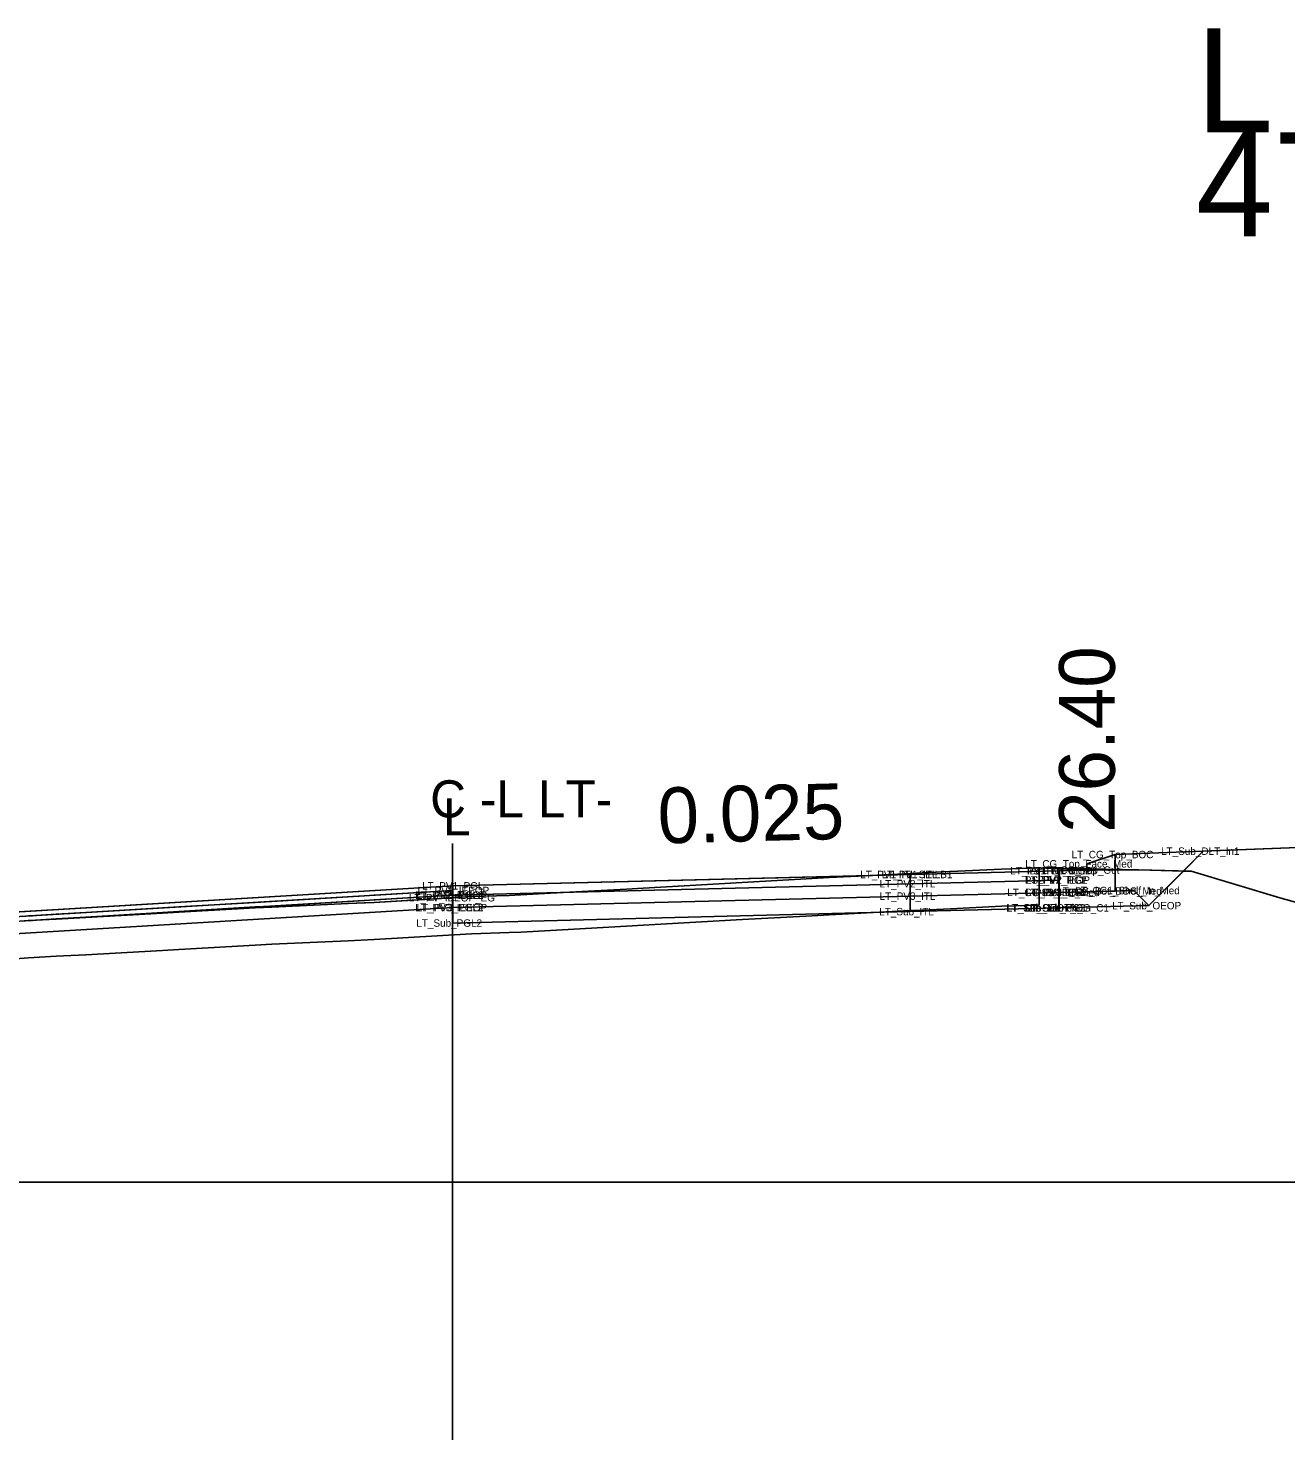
# Model space of a CAD drawing. Extents: x 2177029 to 2201446, y 59897 to 78390.
# Drawn here: x 2200201.31 to 2200235.15, y 68400.38 to 68438.35 of the extents above; entities that cross this region are included whole.
import ezdxf

# ---------------------------------------------------------------- set-up
doc = ezdxf.new("R2010")
doc.units = 0
for name, color, linetype in [('Exist CMT Pavement', 7, 'Continuous'), ('Exist Cross Section Cell', 7, 'Continuous'), ('Exist PHM Roadway Shape', 7, 'Continuous'), ('Exist XS Ground Line', 7, 'Continuous'), ('Old_Level_11', 7, 'Continuous'), ('Prop CMT Conc Surface', 7, 'Continuous'), ('Prop CMT Concrete Structures', 7, 'Continuous'), ('Prop CMT Guardrail Graphics', 7, 'Continuous'), ('Prop CMT Pvmt Course 1', 7, 'Continuous'), ('Prop CMT Pvmt Course 1 CG', 7, 'Continuous'), ('Prop CMT Pvmt Course 2', 7, 'Continuous'), ('Prop CMT Pvmt Course 2 CG', 7, 'Continuous'), ('Prop CMT Pvmt Course 3', 7, 'Continuous'), ('Prop CMT Pvmt Course 4', 7, 'Continuous'), ('Prop CMT Pvmt Surface', 7, 'Continuous'), ('Prop CMT Pvmt Wedge Surface 1', 7, 'Continuous'), ('Prop CMT Slope Grass', 7, 'Continuous'), ('Prop CMT Subgrade Earthwork', 7, 'Continuous'), ('Prop CMT Top Wall Envelope', 7, 'Continuous'), ('Prop Hatching', 7, 'Continuous'), ('Prop Horizontal Alignment', 7, 'Continuous'), ('Prop Retaining Wall', 7, 'Continuous'), ('Prop Terminator CELL', 7, 'Continuous'), ('Prop XS Side Slope Text', 7, 'Continuous'), ('Scratch_Level_0', 7, 'Continuous'), ('Scratch_Level_9', 7, 'Continuous')]:
    doc.layers.add(name, color=color, linetype=linetype)

msp = doc.modelspace()

# ---------------------------------------------------------------- linework, layer by layer
at = {"layer": 'Exist CMT Pavement'}
msp.add_line((2200212.731, 68400.378), (2200212.731, 68416.424), dxfattribs=at)
at = {"layer": 'Exist Cross Section Cell'}
msp.add_line((2200042.732, 68407.31), (2200242.732, 68407.31), dxfattribs=at)
at = {"layer": 'Exist XS Ground Line'}
msp.add_lwpolyline([(2200200.854, 68414.311), (2200201.316, 68414.346), (2200202.064, 68414.385), (2200202.862, 68414.428), (2200204.922, 68414.544), (2200205.363, 68414.569), (2200207.419, 68414.685), (2200207.863, 68414.709), (2200209.917, 68414.802), (2200210.615, 68414.837), (2200213.237, 68414.991), (2200214.251, 68415.022), (2200214.563, 68415.039), (2200215.363, 68415.082), (2200217.409, 68415.195), (2200217.863, 68415.219), (2200219.907, 68415.339), (2200220.363, 68415.365), (2200222.404, 68415.478), (2200222.863, 68415.502), (2200224.902, 68415.607), (2200225.363, 68415.63), (2200226.132, 68415.666), (2200227.498, 68415.73), (2200228.519, 68415.762), (2200231.202, 68415.714), (2200232.605, 68415.672), (2200234.99, 68414.959), (2200242.732, 68412.814)], dxfattribs=at)
at = {"layer": 'Prop CMT Conc Surface'}
for points in [[(2200212.732, 68415.155), (2200186.438, 68413.577)], [(2200212.732, 68415.28), (2200212.732, 68415.03), (2200212.732, 68415.03), (2200212.732, 68415.155)]]:
    msp.add_lwpolyline(points, dxfattribs=at)
at = {"layer": 'Prop CMT Concrete Structures'}
for p, q in [((2200212.732, 68415.28), (2200225.043, 68415.587)), ((2200225.043, 68415.587), (2200225.042, 68415.587)), ((2200229.042, 68415.687), (2200229.05, 68415.688)), ((2200229.05, 68415.688), (2200229.052, 68415.688)), ((2200212.732, 68415.28), (2200176.732, 68413.12))]:
    msp.add_line(p, q, dxfattribs=at)
at = {"layer": 'Prop CMT Guardrail Graphics'}
for points in [[(2200212.732, 68415.28), (2200212.732, 68414.696)], [(2200212.732, 68414.696), (2200176.732, 68412.536)]]:
    msp.add_lwpolyline(points, dxfattribs=at)
at = {"layer": 'Prop CMT Pvmt Course 1'}
for points in [[(2200212.732, 68414.961), (2200210.615, 68414.837), (2200210.363, 68414.822), (2200209.917, 68414.802), (2200207.863, 68414.709), (2200207.419, 68414.685), (2200205.363, 68414.569), (2200204.922, 68414.544), (2200202.862, 68414.428), (2200202.064, 68414.385), (2200201.505, 68414.356), (2200201.424, 68414.351), (2200201.359, 68414.348)], [(2200201.424, 68414.352), (2200201.505, 68414.357), (2200202.064, 68414.39), (2200202.862, 68414.438), (2200204.922, 68414.562), (2200205.363, 68414.588), (2200207.419, 68414.712), (2200207.863, 68414.738), (2200209.917, 68414.861), (2200210.363, 68414.888), (2200210.615, 68414.903), (2200212.732, 68415.03)], [(2200212.732, 68415.03), (2200212.732, 68414.961)], [(2200201.359, 68414.348), (2200201.424, 68414.352)]]:
    msp.add_lwpolyline(points, dxfattribs=at)
at = {"layer": 'Prop CMT Pvmt Course 1 CG'}
for points in [[(2200229.042, 68415.104), (2200225.042, 68415.004)], [(2200225.042, 68415.004), (2200225.042, 68414.587)], [(2200229.042, 68414.687), (2200229.042, 68415.104)], [(2200225.042, 68414.587), (2200229.042, 68414.687)]]:
    msp.add_lwpolyline(points, dxfattribs=at)
at = {"layer": 'Prop CMT Pvmt Course 2'}
for points in [[(2200212.732, 68414.696), (2200225.042, 68415.004)], [(2200225.042, 68415.004), (2200225.042, 68414.587)], [(2200229.042, 68415.104), (2200229.052, 68415.104)], [(2200229.042, 68414.687), (2200229.042, 68415.104)], [(2200229.052, 68415.104), (2200229.052, 68414.688)], [(2200212.732, 68414.28), (2200212.732, 68414.696)], [(2200225.042, 68414.587), (2200212.732, 68414.28)], [(2200229.052, 68414.688), (2200229.042, 68414.687)]]:
    msp.add_lwpolyline(points, dxfattribs=at)
at = {"layer": 'Prop CMT Pvmt Course 2 CG'}
for points in [[(2200212.732, 68415.28), (2200225.042, 68415.587)], [(2200225.042, 68415.587), (2200225.042, 68415.337)], [(2200229.042, 68415.687), (2200229.052, 68415.688)], [(2200229.042, 68415.437), (2200229.042, 68415.687)], [(2200229.052, 68415.688), (2200229.052, 68415.438)], [(2200212.732, 68415.28), (2200176.732, 68413.12)], [(2200186.438, 68413.577), (2200212.732, 68415.155)], [(2200225.042, 68415.337), (2200212.732, 68415.03)], [(2200212.732, 68415.03), (2200212.732, 68415.28)], [(2200212.732, 68415.03), (2200212.732, 68415.28)], [(2200212.732, 68415.155), (2200212.732, 68415.03), (2200212.732, 68415.03)], [(2200229.052, 68415.438), (2200229.042, 68415.437)]]:
    msp.add_lwpolyline(points, dxfattribs=at)
at = {"layer": 'Prop CMT Pvmt Course 3'}
msp.add_line((2200212.732, 68414.961), (2200212.732, 68414.28), dxfattribs=at)
for points in [[(2200232.934, 68416.214), (2200231.468, 68414.748)], [(2200212.732, 68414.28), (2200225.042, 68414.587)], [(2200225.042, 68414.587), (2200229.042, 68414.687)], [(2200229.042, 68414.687), (2200229.052, 68414.688)], [(2200229.052, 68414.688), (2200231.468, 68414.748)], [(2200229.052, 68414.688), (2200229.052, 68414.688)]]:
    msp.add_lwpolyline(points, dxfattribs=at)
at = {"layer": 'Prop CMT Pvmt Course 4'}
msp.add_lwpolyline([(2200225.042, 68415.587), (2200229.042, 68415.687)], dxfattribs=at)
at = {"layer": 'Prop CMT Pvmt Surface'}
for points in [[(2200201.249, 68414.466), (2200201.316, 68414.47), (2200201.424, 68414.477), (2200201.505, 68414.482), (2200202.064, 68414.515), (2200202.862, 68414.563), (2200204.922, 68414.687), (2200205.363, 68414.713), (2200207.419, 68414.837), (2200207.863, 68414.863), (2200209.917, 68414.986), (2200210.363, 68415.013), (2200210.615, 68415.028), (2200212.732, 68415.155)], [(2200212.732, 68415.155), (2200212.732, 68415.03)], [(2200212.732, 68415.03), (2200210.615, 68414.903), (2200210.363, 68414.888), (2200209.917, 68414.861), (2200207.863, 68414.738), (2200207.419, 68414.712), (2200205.363, 68414.588), (2200204.922, 68414.562), (2200202.862, 68414.438), (2200202.064, 68414.39), (2200201.505, 68414.357), (2200201.424, 68414.352), (2200201.359, 68414.348), (2200201.316, 68414.346), (2200201.302, 68414.344)]]:
    msp.add_lwpolyline(points, dxfattribs=at)
at = {"layer": 'Prop CMT Pvmt Wedge Surface 1'}
for p, q in [((2200228.519, 68415.762), (2200228.519, 68414.762)), ((2200220.363, 68414.365), (2200222.404, 68414.478)), ((2200222.404, 68414.478), (2200222.863, 68414.502)), ((2200222.863, 68414.502), (2200224.902, 68414.607)), ((2200224.902, 68414.607), (2200225.363, 68414.63)), ((2200225.363, 68414.63), (2200226.132, 68414.666)), ((2200226.132, 68414.666), (2200227.498, 68414.73)), ((2200227.498, 68414.73), (2200228.519, 68414.762)), ((2200213.237, 68413.991), (2200214.251, 68414.022)), ((2200214.251, 68414.022), (2200214.563, 68414.039)), ((2200214.563, 68414.039), (2200215.363, 68414.082)), ((2200215.363, 68414.082), (2200217.409, 68414.195)), ((2200217.409, 68414.195), (2200217.863, 68414.219)), ((2200217.863, 68414.219), (2200219.907, 68414.339)), ((2200219.907, 68414.339), (2200220.363, 68414.365)), ((2200205.363, 68413.569), (2200207.419, 68413.685)), ((2200207.419, 68413.685), (2200207.863, 68413.709)), ((2200207.863, 68413.709), (2200209.917, 68413.802)), ((2200209.917, 68413.802), (2200210.615, 68413.837)), ((2200210.615, 68413.837), (2200213.237, 68413.991)), ((2200200.854, 68413.311), (2200201.316, 68413.346)), ((2200201.316, 68413.346), (2200202.064, 68413.385)), ((2200202.064, 68413.385), (2200202.862, 68413.428)), ((2200202.862, 68413.428), (2200204.922, 68413.544)), ((2200204.922, 68413.544), (2200205.363, 68413.569))]:
    msp.add_line(p, q, dxfattribs=at)
at = {"layer": 'Prop CMT Slope Grass'}
for points in [[(2200212.732, 68415.03), (2200225.042, 68415.337)], [(2200225.042, 68415.337), (2200225.042, 68415.004)], [(2200229.042, 68415.437), (2200229.052, 68415.438)], [(2200229.042, 68415.104), (2200229.042, 68415.437)], [(2200229.052, 68415.438), (2200229.052, 68415.104)], [(2200212.732, 68414.696), (2200212.732, 68415.03)], [(2200225.042, 68415.004), (2200212.732, 68414.696)], [(2200229.052, 68415.104), (2200229.042, 68415.104)]]:
    msp.add_lwpolyline(points, dxfattribs=at)
at = {"layer": 'Prop CMT Subgrade Earthwork'}
for points in [[(2200212.732, 68415.28), (2200212.732, 68415.03)], [(2200212.732, 68415.03), (2200176.732, 68412.87)]]:
    msp.add_lwpolyline(points, dxfattribs=at)
at = {"layer": 'Prop Hatching'}
msp.add_lwpolyline([(2200230.562, 68416.123), (2200236.887, 68416.366)], dxfattribs=at)
at = {"layer": 'Prop Horizontal Alignment'}
for points in [[(2200229.052, 68415.104), (2200231.062, 68415.155), (2200231.468, 68414.748)], [(2200229.052, 68414.688), (2200229.052, 68415.104)], [(2200231.468, 68414.748), (2200229.052, 68414.688)]]:
    msp.add_lwpolyline(points, dxfattribs=at)
at = {"layer": 'Prop Retaining Wall'}
msp.add_lwpolyline([(2200229.052, 68415.688), (2200229.802, 68415.706), (2200229.803, 68415.873), (2200230.562, 68416.123)], dxfattribs=at)
at = {"layer": 'Prop Terminator CELL'}
for points in [[(2200229.052, 68415.688), (2200229.802, 68415.706), (2200229.803, 68415.873), (2200230.562, 68416.123)], [(2200230.562, 68416.123), (2200230.562, 68415.142)], [(2200229.052, 68415.104), (2200229.052, 68415.688)], [(2200230.562, 68415.142), (2200229.052, 68415.104)]]:
    msp.add_lwpolyline(points, dxfattribs=at)
at = {"layer": 'Prop XS Side Slope Text'}
for points in [[(2200242.732, 68412.814), (2200242.732, 68413.665), (2200242.287, 68413.656), (2200240.245, 68415.698), (2200236.887, 68416.366), (2200232.934, 68416.215), (2200232.398, 68415.678), (2200232.605, 68415.672), (2200234.99, 68414.959)], [(2200220.363, 68415.365), (2200222.404, 68415.478), (2200222.863, 68415.502), (2200224.032, 68415.562), (2200225.042, 68415.587), (2200229.042, 68415.687), (2200229.802, 68415.706), (2200231.202, 68415.714), (2200232.398, 68415.678), (2200231.468, 68414.748), (2200229.052, 68414.688), (2200225.042, 68414.587), (2200212.732, 68414.28), (2200212.732, 68414.961), (2200213.237, 68414.991), (2200214.251, 68415.022), (2200214.563, 68415.039), (2200215.363, 68415.082), (2200217.409, 68415.195), (2200217.863, 68415.219), (2200219.907, 68415.339)], [(2200224.902, 68415.607), (2200225.363, 68415.63), (2200226.132, 68415.666), (2200227.498, 68415.73), (2200228.519, 68415.762), (2200229.802, 68415.706), (2200229.042, 68415.687), (2200225.042, 68415.587), (2200224.032, 68415.562)]]:
    msp.add_lwpolyline(points, close=True, dxfattribs=at)
msp.add_lwpolyline([(2200200.854, 68414.311), (2200201.316, 68414.346), (2200202.064, 68414.385), (2200202.862, 68414.428), (2200204.922, 68414.544), (2200205.363, 68414.569), (2200207.419, 68414.685), (2200207.863, 68414.709), (2200209.917, 68414.802), (2200210.615, 68414.837), (2200212.732, 68414.961), (2200213.237, 68414.991), (2200214.251, 68415.022), (2200214.563, 68415.039), (2200215.363, 68415.082), (2200217.409, 68415.195), (2200217.863, 68415.219), (2200219.907, 68415.339), (2200220.363, 68415.365), (2200222.404, 68415.478), (2200222.863, 68415.502), (2200224.032, 68415.562), (2200212.732, 68415.28), (2200176.722, 68413.119)], dxfattribs=at)
at = {"layer": 'Scratch_Level_0'}
for points in [[(2200225.042, 68415.337), (2200229.042, 68415.437)], [(2200225.042, 68415.004), (2200225.042, 68415.337)], [(2200229.042, 68415.437), (2200229.042, 68415.104)], [(2200229.042, 68415.104), (2200225.042, 68415.004)]]:
    msp.add_lwpolyline(points, dxfattribs=at)
at = {"layer": 'Scratch_Level_9'}
for points in [[(2200225.042, 68415.587), (2200229.042, 68415.687)], [(2200225.042, 68415.337), (2200225.042, 68415.587)], [(2200229.042, 68415.687), (2200229.042, 68415.437)], [(2200229.042, 68415.437), (2200225.042, 68415.337)]]:
    msp.add_lwpolyline(points, dxfattribs=at)

# ---------------------------------------------------------------- texts
at = {"layer": 'Exist CMT Pavement'}
for s, p in [('C -L LT-', (2200212.126, 68417.12)), ('L', (2200212.469, 68416.639))]:
    msp.add_text(s, height=1, dxfattribs=at).set_placement(p)
at = {"layer": 'Exist Cross Section Cell'}
for s, p in [('L', (2200232.732, 68435.554)), ('47+50.00 / 1', (2200232.732, 68432.754))]:
    msp.add_text(s, height=2.8, dxfattribs=at).set_placement(p)
at = {"layer": 'Exist PHM Roadway Shape'}
for s, p in [('LT_Sub_DLT_In1', (2200231.796, 68416.114)), ('LT_CG_Top_Face_Med', (2200228.14, 68415.773)), ('LT_CG_Top_BOC', (2200229.39, 68416.023)), ('LT_PV1_ITL SE LB1', (2200223.698, 68415.487)), ('LT_PV1_ITL', (2200224.278, 68415.487)), ('LT_PV1_ITL SE LB', (2200227.738, 68415.588)), ('PS2_LT_IEOP', (2200228.13, 68415.337)), ('LT_PV2_ITL2', (2200228.141, 68415.338)), ('LT_PV2_PGL', (2200228.163, 68415.337)), ('PS1_LT_IEOP', (2200228.186, 68415.587)), ('LT_PV1_ITL1', (2200228.255, 68415.588)), ('LT_CG_Top_Gut', (2200228.625, 68415.606)), ('LT_PV1_IEEOP', (2200211.784, 68415.055)), ('LT_PV1_PGL', (2200211.91, 68415.18)), ('LT_PV2_ITL', (2200224.221, 68415.237)), ('LT_CG_Bot_IE_Med', (2200227.658, 68415.004)), ('LT_PV3_ITL2', (2200228.141, 68415.004)), ('LT_PV3_PGL', (2200228.163, 68415.004)), ('PS3_IEOP', (2200228.399, 68415.004)), ('LT_CG_Bot_BOC_Med', (2200229.005, 68415.042)), ('LT_CG1_Shelf_In_Med', (2200229.49, 68415.055)), ('LT_PV_IEEOP_EG', (2200211.551, 68414.861)), ('LT_PV2_IEEOP', (2200211.727, 68414.93)), ('LT_PV3_IEEOP', (2200211.727, 68414.596)), ('LT_PV2_PGL2', (2200211.763, 68414.93)), ('LT_PV3_PGL2', (2200211.763, 68414.596)), ('LT_PV3_ITL', (2200224.221, 68414.904)), ('LT_Sub_Trench_In', (2200227.624, 68414.587)), ('LT_Sub_IEOT_CG_C1', (2200227.644, 68414.588)), ('LT_Sub_ITL2', (2200228.132, 68414.588)), ('LT_Sub_PGL', (2200228.153, 68414.587)), ('LT_Sub_OEOP', (2200230.479, 68414.648)), ('LT_Sub_ITL', (2200224.212, 68414.487)), ('LT_Sub_PGL2', (2200211.754, 68414.18))]:
    msp.add_text(s, height=0.2, dxfattribs=at).set_placement(p)
at = {"layer": 'Old_Level_11'}
msp.add_text('0.025', height=1.5, rotation=1.4321, dxfattribs=at).set_placement((2200218.266, 68416.419))
at = {"layer": 'Prop CMT Top Wall Envelope'}
msp.add_text('26.40', height=1.5, rotation=90, dxfattribs=at).set_placement((2200230.552, 68416.706))

doc.saveas('drawing.dxf')
